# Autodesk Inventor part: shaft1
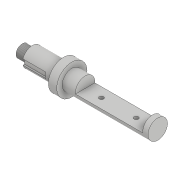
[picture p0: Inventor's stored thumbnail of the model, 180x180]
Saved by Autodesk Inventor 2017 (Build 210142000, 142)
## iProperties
Created: 2016-07
Part Number: shaft1
Material: Generic
Document SubType Name: Modeling
Designer: Sandeep
Density: 1 g/cm^3
Appearance: Default
Author: Sandeep
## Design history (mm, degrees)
sketch "Sketch1"
  geometry: L1 (-125.556, 0)-(92.286, 0); L2 (0, 18)-(28.9, 18); L3 (28.9, 18)-(28.9, 28); L4 (28.9, 28)-(118.7, 28); L5 (118.7, 28)-(118.7, 43.6); L6 (118.7, 43.6)-(142.7, 43.6); L7 (142.7, 43.6)-(142.7, 28); L8 (142.7, 28)-(389.8, 28); L9 (389.8, 28)-(389.8, 0); L10 (0, 18)-(0, 0); L11 (0, 0)-(389.8, 0)
  constraints: 22 end point, 7 perpendicular, 3 point on line, 2 horizontal, 1 collinear
  dimensions: "d0" = 36 diameter of L2 L1; "d1" = 56 diameter of L4 L1; "d2" = 87.2 diameter of L6 L1; "d3" = 28.9 distance between parallel lines of L3 L10; "d5" = 247.1 distance between parallel lines of L9 L7; "d6" = 24 distance between parallel lines of L5 L7; "d7" = 89.8 distance between parallel lines of L3 L5
revolve "Revolution1" sketch "Sketch1" stored, may be unused: angle "d8" = 90 deg
sketch "Sketch5"
  geometry: L1 (-142.7, 28)-(-389.8, 28) reference; L2 (-180.9, 28)-(-374.7, 28); L3 (-374.7, 28)-(-374.7, -3.1); L4 (-374.7, -3.1)-(-180.9, -3.1); L5 (-180.9, -3.1)-(-180.9, 28); L6 (-389.8, 28)-(-389.8, -28) reference; 1 further point
  constraints: 8 end point, 2 parallel, 1 horizontal, 1 perpendicular, 1 point on line
  dimensions: "d18" = 15.1 distance between parallel lines of L6 L3; "d19" = 193.8 distance between parallel lines of L5 L3; "d20" = 24.9 distance from line of L6.end L4
extrude "Extrusion3" cut sketch "Sketch5" stored distance "d21" = 62.5; taper "d22" = 0 deg
sketch "Sketch6"
  geometry: L1 (0, 0.172)-(0, -55.828) reference; L2 (208.9, -55.828)-(208.9, 0.172) reference; L3 (208.9, -27.828)-(-12.149, -27.828); C1 r 6.25 at (146.9, -27.828); C2 r 6.25 at (46.9, -27.828); 3 further points
  constraints: 2 centre point, 2 end point, 2 point on line, 1 equal radius, 1 horizontal, 1 midpoint
  dimensions: "d23" = 100 distance of C1.centre C2.centre; "d24" = 12.5 diameter of C2; "d25" = 46.9 distance from line of L1 C2.centre
extrude "Extrusion4" cut sketch "Sketch6" distance "d26" = 62.5; taper "d27" = 0 deg
thread "Thread1" dims "d28" = 10, "d29" = 0
sketch "Sketch9"
  geometry: L1 (-8, -26.833)-(-8, -22); L2 (-8, -22)-(8, -22); L3 (8, -22)-(8, -26.833); L4 (0, 0)-(0, -22.852); A1 r 28 centre (0, 0) between (8, -26.833) and (-8, -26.833) reference; 2 further points
  constraints: 8 end point, 3 point on circle, 1 parallel, 1 vertical, 1 other
  dimensions: "d34" = 16 distance between parallel lines of L1 L3; "d35" = 50 dimension on A1 L2
extrude "Extrusion5" cut sketch "Sketch9" distance "d36" = 66; taper "d37" = 0 deg
body "Solid1"
